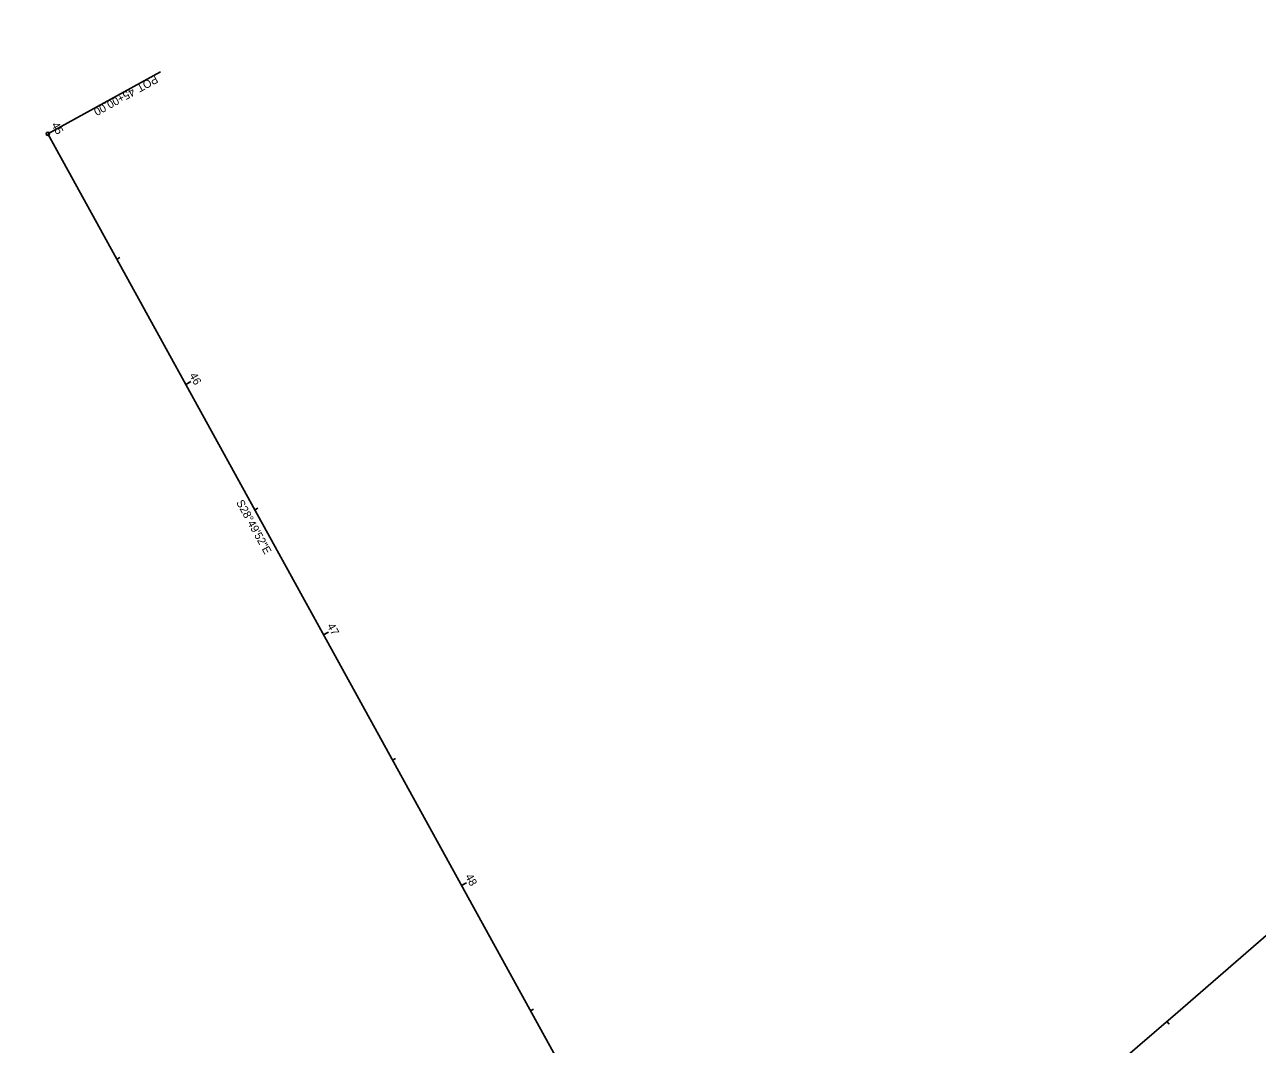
# Model space of a CAD drawing. Extents: x 1492452 to 1496782, y 514026 to 517659.
# Drawn here: x 1494046.8 to 1494477.9, y 515476.4 to 515833 of the extents above; entities that cross this region are included whole.
import ezdxf

# ---------------------------------------------------------------- set-up
doc = ezdxf.new("R2010")
doc.units = 0
for name, color, linetype in [('Default', 7, 'Continuous'), ('DT_X_Contour_Minor', 7, 'Continuous'), ('DT_X_TIN_Hull', 7, 'Continuous'), ('GE_X_Cells', 7, 'Continuous'), ('PV_X_EOP', 7, 'Continuous'), ('PV_X_Shoulder_Aggregate', 7, 'Continuous'), ('RD_X_GR_Rt', 7, 'Continuous'), ('RD_X_Wall', 7, 'Continuous'), ('SV_X_Toe_of_Slope', 7, 'Continuous'), ('SV_X_Top_of_Bank', 7, 'Continuous'), ('XS_X_Ground_Line', 7, 'Continuous')]:
    doc.layers.add(name, color=color, linetype=linetype)

msp = doc.modelspace()

# ---------------------------------------------------------------- linework, layer by layer
at = {"layer": 'Default'}
msp.add_arc((1486425.91, 524780.42), 12277.67, 302.444021, 313.600151, dxfattribs=at)
at = {"layer": 'DT_X_Contour_Minor'}
msp.add_line((1494054.87, 515794.8), (1494055.93, 515795.38), dxfattribs=at)
at = {"layer": 'DT_X_TIN_Hull'}
msp.add_line((1494446.24, 515484.43), (1494447.03, 515483.52), dxfattribs=at)
at = {"layer": 'GE_X_Cells'}
msp.add_arc((1486425.91, 524780.42), 12277.67, 302.444021, 313.600151, dxfattribs=at)
at = {"layer": 'PV_X_EOP'}
msp.add_line((1494054.87, 515794.8), (1494094.3, 515816.5), dxfattribs=at)
msp.add_circle((1494054.87, 515794.8), 0.6, dxfattribs=at)
at = {"layer": 'PV_X_Shoulder_Aggregate'}
for p, q in [((1494054.87, 515794.8), (1494056.63, 515795.76)), ((1494078.99, 515751), (1494080.04, 515751.58)), ((1494103.1, 515707.2), (1494104.85, 515708.16)), ((1494127.21, 515663.39), (1494128.26, 515663.97)), ((1494151.32, 515619.59), (1494153.07, 515620.56)), ((1494175.43, 515575.79), (1494176.48, 515576.37)), ((1494199.54, 515531.99), (1494201.3, 515532.95)), ((1494223.66, 515488.18), (1494224.71, 515488.76))]:
    msp.add_line(p, q, dxfattribs=at)
at = {"layer": 'RD_X_GR_Rt'}
msp.add_line((1494054.87, 515794.8), (1494094.3, 515816.5), dxfattribs=at)
msp.add_circle((1494054.87, 515794.8), 0.6, dxfattribs=at)
at = {"layer": 'RD_X_Wall'}
for p, q in [((1494054.87, 515794.8), (1494056.63, 515795.76)), ((1494103.1, 515707.2), (1494104.15, 515707.77)), ((1494151.32, 515619.59), (1494152.37, 515620.17)), ((1494199.54, 515531.99), (1494200.6, 515532.57))]:
    msp.add_line(p, q, dxfattribs=at)
at = {"layer": 'SV_X_Top_of_Bank'}
for q in [(1494370, 515222.33), (1494370.94, 515220.63)]:
    msp.add_line((1494054.87, 515794.8), q, dxfattribs=at)
at = {"layer": 'XS_X_Ground_Line'}
msp.add_line((1494054.87, 515794.8), (1494094.3, 515816.5), dxfattribs=at)
msp.add_circle((1494054.87, 515794.8), 0.6, dxfattribs=at)

# ---------------------------------------------------------------- texts
at = {"layer": 'PV_X_EOP'}
for s, p in [('POT', (1494092.39, 515815.39)), ('45+00.00', (1494084.39, 515810.99))]:
    msp.add_text(s, height=2.8, rotation=208.8312, dxfattribs=at).set_placement(p)
at = {"layer": 'PV_X_Shoulder_Aggregate'}
for s, p in [('45', (1494056.04, 515797.96)), ('46', (1494104.27, 515710.35)), ('47', (1494152.43, 515622.77)), ('48', (1494200.72, 515535.13))]:
    msp.add_text(s, height=2.8, rotation=298.8312, dxfattribs=at).set_placement(p)
at = {"layer": 'RD_X_GR_Rt'}
for s, p in [('POT', (1494092.39, 515815.39)), ('45+00.00', (1494084.39, 515810.99))]:
    msp.add_text(s, height=2.8, rotation=208.8312, dxfattribs=at).set_placement(p)
at = {"layer": 'RD_X_Wall'}
msp.add_text('45', height=2.8, rotation=298.8312, dxfattribs=at).set_placement((1494056.04, 515797.96))
at = {"layer": 'SV_X_Toe_of_Slope'}
msp.add_text('S28°49\'52"E', height=2.8, rotation=298.8312, dxfattribs=at).set_placement((1494120.65, 515665.91))
at = {"layer": 'XS_X_Ground_Line'}
for s, p in [('POT', (1494092.39, 515815.39)), ('45+00.00', (1494084.39, 515810.99))]:
    msp.add_text(s, height=2.8, rotation=208.8312, dxfattribs=at).set_placement(p)

doc.saveas('drawing.dxf')
